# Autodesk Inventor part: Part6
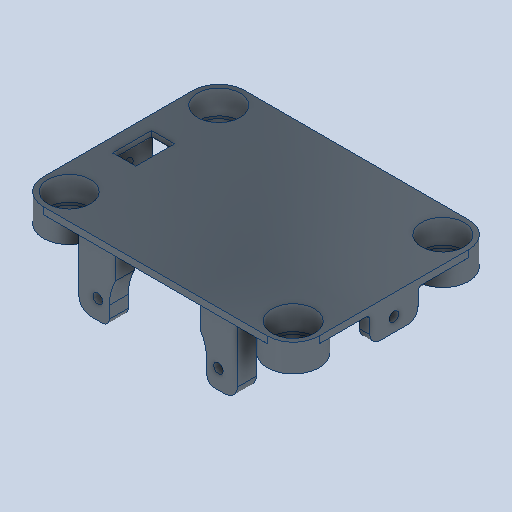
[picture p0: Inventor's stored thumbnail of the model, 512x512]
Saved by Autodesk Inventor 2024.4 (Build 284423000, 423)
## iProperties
Created: 2025-07
Part Number: Part6
Material: Generic
Document SubType Name: Modeling
Designer: AdminForWorker
Density: 1 g/cm^3
Appearance: Default
Author: AdminForWorker
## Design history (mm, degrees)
feature "Body1"
body "Solid1"
